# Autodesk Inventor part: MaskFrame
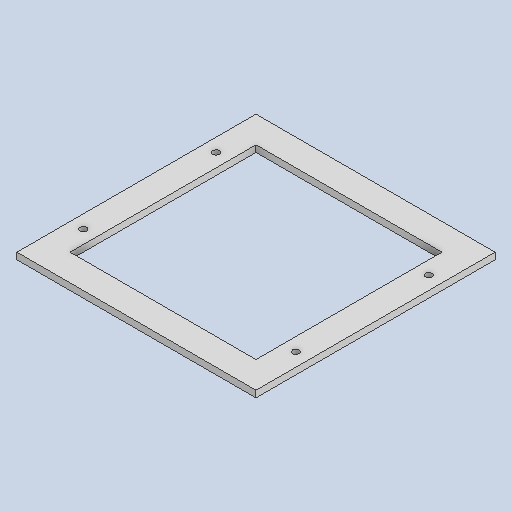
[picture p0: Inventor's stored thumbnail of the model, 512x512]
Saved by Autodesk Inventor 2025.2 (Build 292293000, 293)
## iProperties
Created: 2025-09
Part Number: MaskFrame
Material: Generic
Document SubType Name: Modeling
Designer: tyler
Density: 1 g/cm^3
Appearance: Default
Author: tyler
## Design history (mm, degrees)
sketch "Sketch1"
  geometry: L1 (88.9, 88.9)-(-88.9, 88.9); L2 (-88.9, 88.9)-(-88.9, -88.9); L3 (-88.9, -88.9)-(88.9, -88.9); L4 (88.9, -88.9)-(88.9, 88.9); L5 (88.9, 88.9)-(-88.9, -88.9); L6 (-88.9, 88.9)-(88.9, -88.9); L7 (-114.3, -114.3)-(114.3, -114.3); L8 (114.3, -114.3)-(114.3, 114.3); L9 (114.3, 114.3)-(-114.3, 114.3); L10 (-114.3, 114.3)-(-114.3, -114.3); L11 (-114.3, -114.3)-(114.3, 114.3); L12 (114.3, -114.3)-(-114.3, 114.3); 1 further point
  constraints: 24 end point, 4 midpoint, 4 parallel, 2 horizontal, 2 perpendicular
  dimensions: "d0" = 177.8 distance of L3.end L2.end; "d1" = 177.8 distance of L2.end L1.end; "d2" = 228.6 distance of L9.end L8.end; "d3" = 228.6 distance of L8.end L7.end
extrude "Extrusion1" new body sketch "Sketch1" distance "d4" = 6.35; taper "d5" = 0 deg
sketch "Sketch2"
  geometry: L1 (101.6, -101.6)-(-101.6, -101.6); L2 (-101.6, -101.6)-(-101.6, 101.6); L3 (-101.6, 101.6)-(101.6, 101.6); L4 (101.6, 101.6)-(101.6, -101.6); L5 (101.6, -101.6)-(-101.6, 101.6); L6 (-101.6, -101.6)-(101.6, 101.6); C1 r 6.35 at (-101.6, 101.6); C2 r 6.35 at (101.6, 101.6); C3 r 6.35 at (-101.6, -101.6); C4 r 6.35 at (101.6, -101.6); 1 further point
  constraints: 12 end point, 4 centre point, 4 coincident, 2 midpoint, 2 parallel, 1 horizontal, 1 perpendicular
  dimensions: "d6" = 203.2 distance of L2.end L3.end; "d7" = 203.2 distance of L1.end L2.end; "d8" = 12.7 diameter of C1; "d9" = 12.7 diameter of C2; "d10" = 12.7 diameter of C3; "d11" = 12.7 diameter of C4
extrude "Extrusion2" cut sketch "Sketch2" distance "d12" = 3.175; taper "d13" = 0 deg
sketch "Sketch3"
  geometry: L1 (-114.3, 114.3)-(-114.3, -114.3) reference; L2 (-114.3, 0)-(-101.6, 0); L3 (-101.6, 0)-(-101.6, 63.5); L4 (0, 0)-(0, 9.353); C1 r 3.175 at (-101.6, 63.5); C2 r 3.175 at (-101.6, -63.5); C3 r 3.175 at (101.6, 63.5); C4 r 3.175 at (101.6, -63.5)
  constraints: 6 end point, 4 centre point, 3 symmetric about line, 1 coincident, 1 horizontal, 1 midpoint, 1 perpendicular, 1 vertical, 3 other
  dimensions: "d14" = 12.7 distance of L2.start L2.end; "d15" = 63.5 distance of L2.end L3.end; "d16" = 6.35 diameter of C1
extrude "Extrusion3" cut sketch "Sketch3" distance "d17" = 25.4; taper "d18" = 0 deg
body "Solid1"
